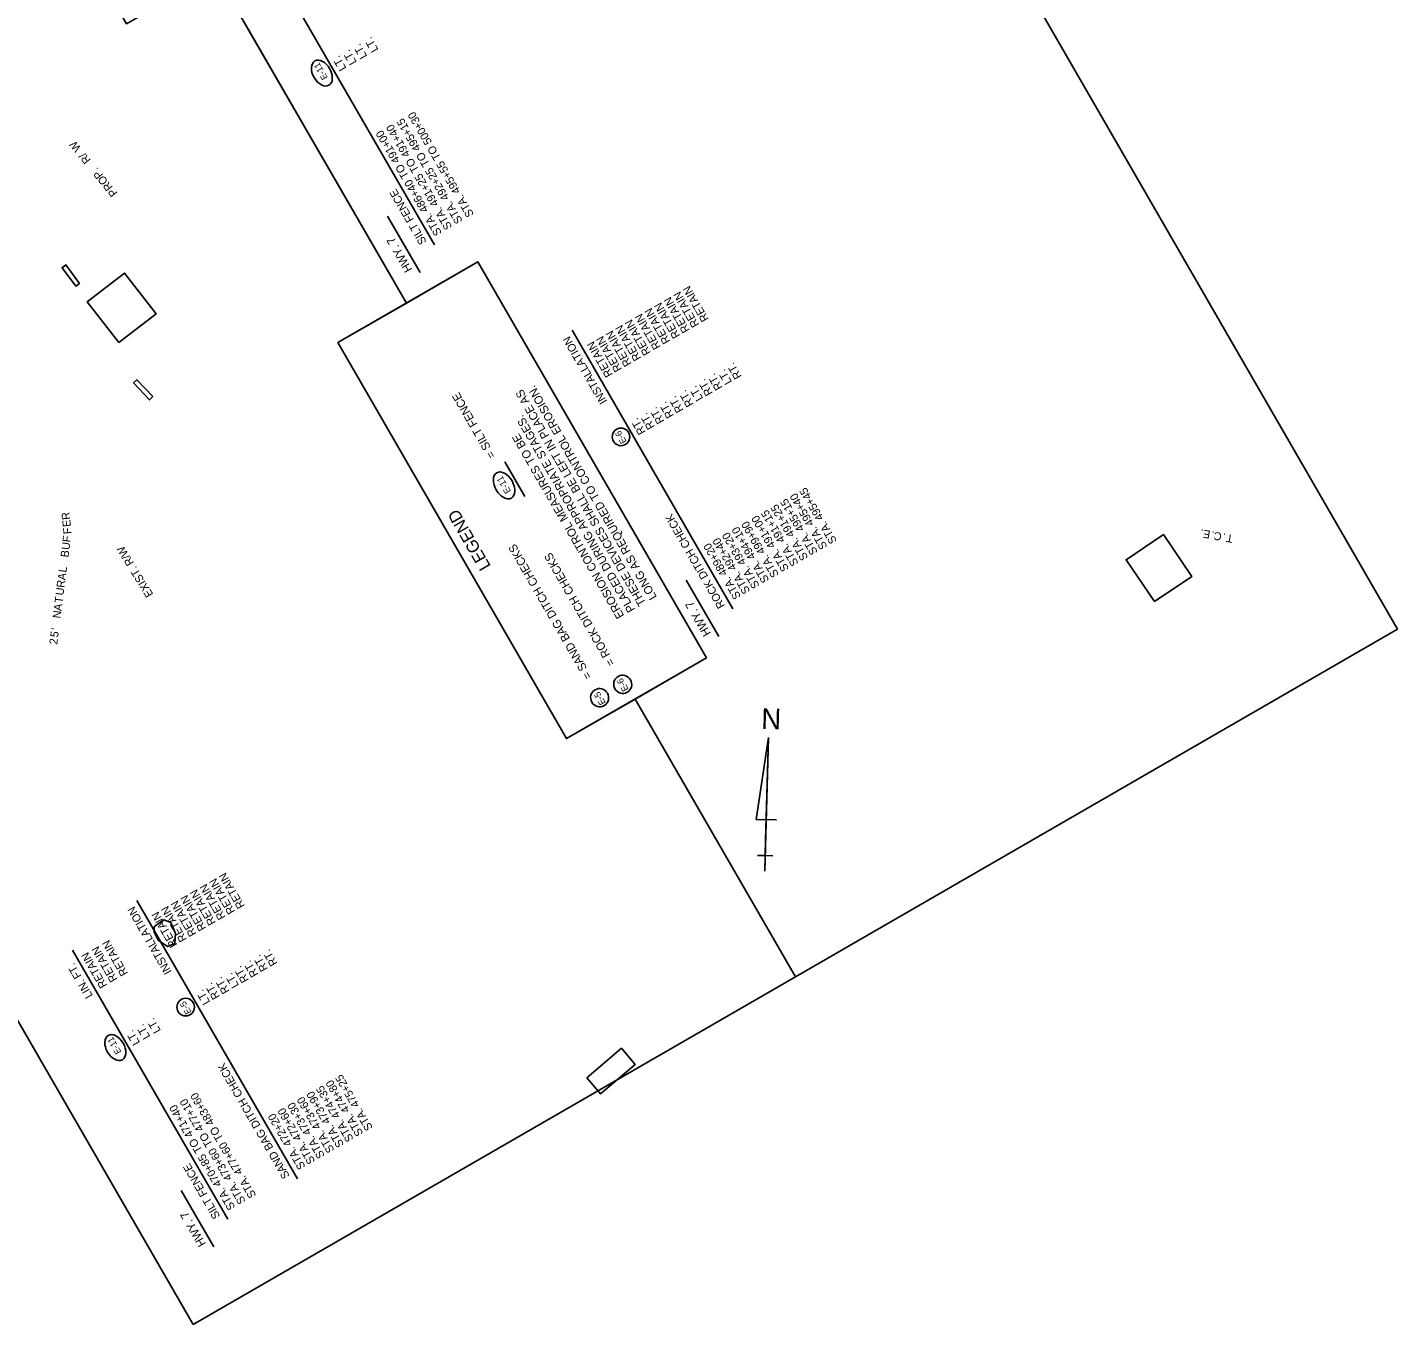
# Model space of a CAD drawing. Extents: x 956270 to 957915, y 1920520 to 1922423.
# Drawn here: x 956888 to 957915, y 1920520 to 1921493 of the extents above; entities that cross this region are included whole.
import ezdxf

# ---------------------------------------------------------------- set-up
doc = ezdxf.new("R2010")
doc.units = 0
for name, color, linetype in [('1', 7, 'Continuous'), ('44', 7, 'Continuous'), ('63', 7, 'Continuous'), ('Level 1', 7, 'Continuous'), ('Level 44', 7, 'Continuous'), ('NO PLOT', 7, 'Continuous'), ('R_Draft', 7, 'Continuous'), ('S_TREE', 7, 'Continuous')]:
    doc.layers.add(name, color=color, linetype=linetype)

msp = doc.modelspace()

# ---------------------------------------------------------------- linework, layer by layer
at = {"layer": '1'}
for p, q in [((957172.3, 1921286.1), (957029.2, 1921533.9)), ((957225.7, 1921317), (957120.9, 1921256.4)), ((957292.2, 1920959.7), (957120.9, 1921256.4)), ((957367.7, 1921003.2), (957292.2, 1920959.7)), ((957463.8, 1920781), (957343.6, 1920989.3))]:
    msp.add_line(p, q, dxfattribs=at)
msp.add_lwpolyline([(957367.7, 1921003.2), (957397.1, 1921020.2), (957225.7, 1921317)], dxfattribs=at)
for centre in [(957333.1, 1921185.8), (957006.8, 1920758.4)]:
    msp.add_circle(centre, 6.61, dxfattribs=at)
for centre in [(957108.9, 1921458.4), (956954.1, 1920728.1)]:
    msp.add_ellipse(centre, major_axis=(-5.26, 9.11), ratio=0.638788, dxfattribs=at)
at = {"layer": '44'}
for p, q in [((957193.2, 1921329.7), (957076.8, 1921531.3)), ((957182.6, 1921309), (957158.2, 1921351.3)), ((957417, 1921057), (957296.5, 1921265.7)), ((957406.4, 1921036.2), (957381.9, 1921078.5)), ((957090.6, 1920629.6), (956970.1, 1920838.3)), ((957038.5, 1920599.4), (956922.1, 1920801.1)), ((957027.9, 1920578.7), (957003.5, 1920621))]:
    msp.add_line(p, q, dxfattribs=at)
at = {"layer": '63'}
for p, q in [((957443.6, 1920960.4), (957434.3, 1920899.1)), ((957440.9, 1920860.4), (957443.6, 1920960.4)), ((957443.6, 1920960.4), (957441.5, 1920883.5)), ((957434.3, 1920899.1), (957449.6, 1920898.7)), ((957440.9, 1920860.4), (957441.5, 1920883.5)), ((957441.2, 1920872), (957435.5, 1920872.1)), ((957435.5, 1920872.1), (957447, 1920871.8)), ((957440.9, 1920860.4), (957441.2, 1920872))]:
    msp.add_line(p, q, dxfattribs=at)
at = {"layer": 'Level 1'}
for centre, major_axis, ratio in [((957245.5, 1921149.4), (-5.48, 9.49), 0.622952), ((957334.4, 1921000.3), (3.44, -5.96), 0.97521), ((957317.1, 1920990.3), (3.44, -5.96), 0.97521)]:
    msp.add_ellipse(centre, major_axis=major_axis, ratio=ratio, dxfattribs=at)
at = {"layer": 'Level 44'}
msp.add_lwpolyline([(957261.1, 1921141), (957246, 1921167.1)], dxfattribs=at)
at = {"layer": 'NO PLOT'}
for points in [[(957915.2, 1921041.6), (957117.5, 1922423.2), (956666.2, 1922162.6), (956816.7, 1921902), (956875.1, 1921935.7), (957087.6, 1921567.7), (957029.2, 1921533.9), (957172.3, 1921286.1), (957225.7, 1921317), (957397.1, 1921020.2), (957343.6, 1920989.3), (957463.8, 1920781)], [(957915.2, 1921041.6), (957117.5, 1922423.2), (956666.2, 1922162.6), (956816.7, 1921902), (956875.1, 1921935.7), (957087.6, 1921567.7), (957029.2, 1921533.9), (957172.3, 1921286.1), (957225.7, 1921317), (957397.1, 1921020.2), (957343.6, 1920989.3), (957463.8, 1920781)], [(957915.2, 1921041.6), (957117.5, 1922423.2), (956666.2, 1922162.6), (956816.7, 1921902), (956875.1, 1921935.7), (957087.6, 1921567.7), (957029.2, 1921533.9), (957172.3, 1921286.1), (957225.7, 1921317), (957397.1, 1921020.2), (957343.6, 1920989.3), (957463.8, 1920781)], [(957915.2, 1921041.6), (957117.5, 1922423.2), (956666.2, 1922162.6), (956816.7, 1921902), (956875.1, 1921935.7), (957087.6, 1921567.7), (957029.2, 1921533.9), (957172.3, 1921286.1), (957225.7, 1921317), (957397.1, 1921020.2), (957343.6, 1920989.3), (957463.8, 1920781)], [(957915.2, 1921041.6), (957117.5, 1922423.2), (956666.2, 1922162.6), (956816.7, 1921902), (956875.1, 1921935.7), (957087.6, 1921567.7), (957029.2, 1921533.9), (957172.3, 1921286.1), (957225.7, 1921317), (957397.1, 1921020.2), (957343.6, 1920989.3), (957463.8, 1920781)], [(957915.2, 1921041.6), (957117.5, 1922423.2), (956666.2, 1922162.6), (956816.7, 1921902), (956875.1, 1921935.7), (957087.6, 1921567.7), (957029.2, 1921533.9), (957172.3, 1921286.1), (957225.7, 1921317), (957397.1, 1921020.2), (957343.6, 1920989.3), (957463.8, 1920781)], [(957012.5, 1920520.4), (956420.5, 1921545.9), (956463.3, 1921570.6), (956365.4, 1921740.1), (956378, 1921747.4), (956270.3, 1921934.1), (956666.2, 1922162.6), (956816.7, 1921902), (956750, 1921863.5), (956962.5, 1921495.4), (957029.2, 1921533.9), (957172.3, 1921286.1), (957120.9, 1921256.4), (957292.2, 1920959.7), (957343.6, 1920989.3), (957463.8, 1920781)], [(957012.5, 1920520.4), (956420.5, 1921545.9), (956463.3, 1921570.6), (956365.4, 1921740.1), (956378, 1921747.4), (956270.3, 1921934.1), (956666.2, 1922162.6), (956816.7, 1921902), (956750, 1921863.5), (956962.5, 1921495.4), (957029.2, 1921533.9), (957172.3, 1921286.1), (957120.9, 1921256.4), (957292.2, 1920959.7), (957343.6, 1920989.3), (957463.8, 1920781)], [(957012.5, 1920520.4), (956420.5, 1921545.9), (956463.3, 1921570.6), (956365.4, 1921740.1), (956378, 1921747.4), (956270.3, 1921934.1), (956666.2, 1922162.6), (956816.7, 1921902), (956750, 1921863.5), (956962.5, 1921495.4), (957029.2, 1921533.9), (957172.3, 1921286.1), (957120.9, 1921256.4), (957292.2, 1920959.7), (957343.6, 1920989.3), (957463.8, 1920781)], [(957012.5, 1920520.4), (956420.5, 1921545.9), (956463.3, 1921570.6), (956365.4, 1921740.1), (956378, 1921747.4), (956270.3, 1921934.1), (956666.2, 1922162.6), (956816.7, 1921902), (956750, 1921863.5), (956962.5, 1921495.4), (957029.2, 1921533.9), (957172.3, 1921286.1), (957120.9, 1921256.4), (957292.2, 1920959.7), (957343.6, 1920989.3), (957463.8, 1920781)], [(957012.5, 1920520.4), (956420.5, 1921545.9), (956463.3, 1921570.6), (956365.4, 1921740.1), (956378, 1921747.4), (956270.3, 1921934.1), (956666.2, 1922162.6), (956816.7, 1921902), (956750, 1921863.5), (956962.5, 1921495.4), (957029.2, 1921533.9), (957172.3, 1921286.1), (957120.9, 1921256.4), (957292.2, 1920959.7), (957343.6, 1920989.3), (957463.8, 1920781)], [(957012.5, 1920520.4), (956420.5, 1921545.9), (956463.3, 1921570.6), (956365.4, 1921740.1), (956378, 1921747.4), (956270.3, 1921934.1), (956666.2, 1922162.6), (956816.7, 1921902), (956750, 1921863.5), (956962.5, 1921495.4), (957029.2, 1921533.9), (957172.3, 1921286.1), (957120.9, 1921256.4), (957292.2, 1920959.7), (957343.6, 1920989.3), (957463.8, 1920781)], [(956927.3, 1921300.8), (956917, 1921314.7), (956914.2, 1921312.6), (956924.5, 1921298.7)], [(956956.7, 1921256.4), (956984.6, 1921277.9), (956961, 1921308.5), (956933.1, 1921287)], [(956982.3, 1921216), (956970.3, 1921228.6), (956967.8, 1921226.2), (956979.7, 1921213.5)], [(957733, 1921062.3), (957761, 1921081.2), (957739.7, 1921112.6), (957711.7, 1921093.7)], [(957307.4, 1920705.3), (957333.4, 1920727.6), (957343.7, 1920715.5), (957317.7, 1920693.3)]]:
    msp.add_lwpolyline(points, close=True, dxfattribs=at)
at = {"layer": 'S_TREE'}
msp.add_lwpolyline([(956983.6, 1920819.1), (956990.4, 1920823.8), (956995.6, 1920821.9), (956999.3, 1920813.6), (956998.7, 1920806), (956993.3, 1920803.8), (956986.3, 1920808.5), (956983.3, 1920814.5), (956983.3, 1920818.2), (956984.2, 1920819.6)], dxfattribs=at)

# ---------------------------------------------------------------- texts
at = {"layer": '1'}
for s, p in [('E-11', (957113.5, 1921455.1)), ('E-6 ', (957337.5, 1921182.3)), ('E-5 ', (957011.3, 1920754.7)), ('E-11', (956958.8, 1920724.8))]:
    msp.add_text(s, height=4.8, rotation=120, dxfattribs=at).set_placement(p)
at = {"layer": '44'}
for s, height, p in [('LT.', 6, (957151.5, 1921476)), ('LT.', 6, (957127.5, 1921462.1)), ('LT.', 6, (957135.2, 1921466.6)), ('LT.', 6, (957143.1, 1921471.1)), ('STA. 491+25 TO 491+40', 6, (957206.7, 1921343.1)), ('STA. 492+25 TO 495+15', 6, (957214.6, 1921347.6)), ('STA. 495+55 TO 500+30', 6, (957223, 1921352.5)), ('STA. 486+40 TO 491+00', 6, (957199, 1921338.6)), ('SILT FENCE      ', 6, (957187.6, 1921332)), ('HWY. 7', 6.25, (957176.9, 1921311.3)), ('RETAIN', 6, (957399.1, 1921274.1)), ('RETAIN', 6, (957377.6, 1921261.6)), ('RETAIN', 6, (957384.8, 1921265.8)), ('RETAIN', 6, (957391.9, 1921269.9)), ('RETAIN', 6, (957363.1, 1921253.3)), ('RETAIN', 6, (957370.3, 1921257.5)), ('RETAIN', 6, (957348.4, 1921244.8)), ('RETAIN', 6, (957355.6, 1921248.9)), ('INSTALLATION', 6, (957322.9, 1921212.4)), ('RETAIN', 6, (957327.1, 1921232.5)), ('RETAIN', 6, (957334, 1921236.5)), ('RETAIN', 6, (957341.2, 1921240.6)), ('LT.', 6, (957416.5, 1921227)), ('RT.', 6, (957423.8, 1921231.1)), ('RT.', 6, (957402.2, 1921218.6)), ('RT.', 6, (957409.4, 1921222.8)), ('RT.', 6, (957380.2, 1921205.9)), ('RT.', 6, (957387.8, 1921210.3)), ('LT.', 6, (957394.9, 1921214.6)), ('RT.', 6, (957358.6, 1921193.4)), ('RT.', 6, (957365.8, 1921197.6)), ('RT.', 6, (957373, 1921201.8)), ('RT.', 6, (957351.8, 1921189.5)), ('STA. 495+40', 6, (957488, 1921103.5)), ('STA. 495+45', 6, (957495.2, 1921107.7)), ('STA. 491+25', 6, (957473.6, 1921095.2)), ('STA. 495+15', 6, (957480.8, 1921099.4)), ('ROCK DITCH CHECK', 6, (957411.3, 1921059.2)), ('STA. 499+90', 6, (957451.6, 1921082.5)), ('STA. 491+00', 6, (957459.2, 1921086.9)), ('STA. 491+15', 6, (957466.4, 1921091)), ('STA. 493+20', 6, (957437.2, 1921074.2)), ('STA. 494+10', 6, (957444.4, 1921078.4)), ('STA. 489+20', 6, (957423.2, 1921066.1)), ('STA. 492+40', 6, (957430.1, 1921070.1)), ('HWY. 7', 6.25, (957400.7, 1921038.5)), ('RETAIN', 6, (957044.1, 1920830.1)), ('RETAIN', 6, (957051.3, 1920834.3)), ('RETAIN', 6, (957029.6, 1920821.8)), ('RETAIN', 6, (957036.9, 1920825.9)), ('RETAIN', 6, (957015.2, 1920813.4)), ('RETAIN', 6, (957022.4, 1920817.6)), ('INSTALLATION', 6, (956996.6, 1920785)), ('RETAIN', 6, (957000.8, 1920805.1)), ('RETAIN', 6, (957008, 1920809.3)), ('RETAIN', 6, (956955.9, 1920779.2)), ('RETAIN', 6, (956963.8, 1920783.8)), ('RETAIN', 6, (956948.2, 1920774.7)), ('RT.', 6, (957061.5, 1920782.9)), ('RT.', 6, (957068.7, 1920787.1)), ('RT.', 6, (957075.9, 1920791.2)), ('LIN. FT.', 6, (956937.4, 1920767)), ('LT.', 6, (957047, 1920774.7)), ('RT.', 6, (957054.3, 1920778.7)), ('RT.', 6, (957032.6, 1920766.2)), ('RT.', 6, (957039.9, 1920770.4)), ('LT.', 6, (957025.4, 1920762.2)), ('LT.', 6, (956980.5, 1920736.3)), ('LT.', 6, (956988.4, 1920740.8)), ('LT.', 6, (956972.8, 1920731.8)), ('SAND BAG DITCH CHECK', 6, (957085, 1920631.8)), ('STA. 474+80', 6, (957140.1, 1920663.7)), ('STA. 475+25', 6, (957147.3, 1920667.8)), ('STA. 477+60 TO 483+60', 6, (957059.9, 1920617.3)), ('STA. 473+60', 6, (957118.5, 1920651.2)), ('STA. 473+90', 6, (957125.7, 1920655.3)), ('STA. 474+35', 6, (957132.9, 1920659.5)), ('STA. 470+85 TO 471+40', 6, (957044.2, 1920608.3)), ('STA. 473+60 TO 477+10', 6, (957052, 1920612.8)), ('STA. 472+60', 6, (957104.1, 1920642.8)), ('STA. 473+30', 6, (957111.3, 1920647)), ('STA. 472+20', 6, (957096.8, 1920638.7)), ('SILT FENCE      ', 6, (957032.9, 1920601.7)), ('HWY. 7', 6.25, (957022.2, 1920581))]:
    msp.add_text(s, height=height, rotation=120, dxfattribs=at).set_placement(p)
at = {"layer": '63'}
msp.add_text('N', height=15.4, rotation=358.5016, dxfattribs=at).set_placement((957438.1, 1920967))
at = {"layer": 'Level 1'}
for s, height, p in [('= SILT FENCE', 6.25, (957239.3, 1921171.7)), ('THESE DEVICES SHALL BE LEFT IN PLACE AS ', 6.25, (957352, 1921061.1)), ('LONG AS REQUIRED TO CONTROL EROSION.', 6.25, (957360.2, 1921065.8)), ('PLACED DURING APPROPRIATE STAGES. ', 6.25, (957343.9, 1921056.4)), ('EROSION CONTROL MEASURES TO BE', 6.25, (957335.7, 1921051.7)), ('E-11 ', 4.88, (957250.8, 1921145)), ('= SAND BAG DITCH CHECKS', 6.25, (957311.5, 1921006.2)), ('= ROCK DITCH CHECKS', 6.25, (957328.8, 1921016.2)), ('E-6 ', 4.88, (957339, 1920996.7)), ('E-5 ', 4.88, (957321.8, 1920986.5))]:
    msp.add_text(s, height=height, rotation=120, dxfattribs=at).set_placement(p)
at = {"layer": 'Level 44'}
msp.add_text('LEGEND', height=9.14, rotation=120, dxfattribs=at).set_placement((957235.8, 1921088.9))
at = {"layer": 'R_Draft'}
for s, rotation, p in [('W', 129.1474, (956928.7, 1921402.3)), ('/', 129.1474, (956932.4, 1921397.8)), ('R', 129.1474, (956936, 1921393.4)), ('P', 129.1474, (956945.2, 1921382.1)), ('.', 129.1474, (956941.6, 1921386.5)), ('O', 129.1474, (956948.9, 1921377.5)), ('R', 129.1474, (956952.5, 1921373.1)), ('P', 129.1474, (956956.1, 1921368.7)), ('R', 95.8222, (956920.2, 1921123.9)), ('E', 95.8222, (956920.8, 1921118.6)), ('F', 82.6936, (956920.3, 1921106.5)), ('F', 95.8222, (956921.3, 1921113.2)), ('.', 169.8911, (957769.9, 1921116.2)), ('E', 169.8911, (957775.2, 1921115.3)), ('.', 169.8911, (957778.1, 1921114.7)), ('C', 169.8911, (957783.7, 1921113.7)), ('.', 169.8911, (957786.6, 1921113.2)), ('T', 169.8911, (957792.3, 1921112.2)), ('U', 82.6936, (956919.6, 1921100.8)), ('EXIST. R/W', 121.503, (956982.7, 1921067.8)), ('B', 82.6936, (956918.9, 1921095.2)), ('A', 82.6936, (956916.7, 1921078.1)), ('L', 82.6936, (956917.4, 1921083.9)), ('U', 82.6936, (956915.2, 1921066.7)), ('R', 82.6936, (956915.9, 1921072.4)), ('A', 82.6936, (956913.7, 1921055.1)), ('T', 82.6936, (956914.5, 1921060.9)), ('N', 82.6936, (956913, 1921049.5)), ('5', 82.6936, (956911.2, 1921035.3)), ("'", 82.6936, (956911.9, 1921040.6)), ('2', 82.6936, (956910.5, 1921029.9))]:
    msp.add_text(s, height=6, rotation=rotation, dxfattribs=at).set_placement(p)

doc.saveas('drawing.dxf')
